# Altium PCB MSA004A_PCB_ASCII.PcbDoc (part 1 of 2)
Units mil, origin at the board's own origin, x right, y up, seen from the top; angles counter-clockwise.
Board outline 2300 x 2720 mil, 2 copper layers (Top Layer, Bottom Layer), stack 62 mil thick; 117 components, 85 nets, 350 pads, 179 vias.
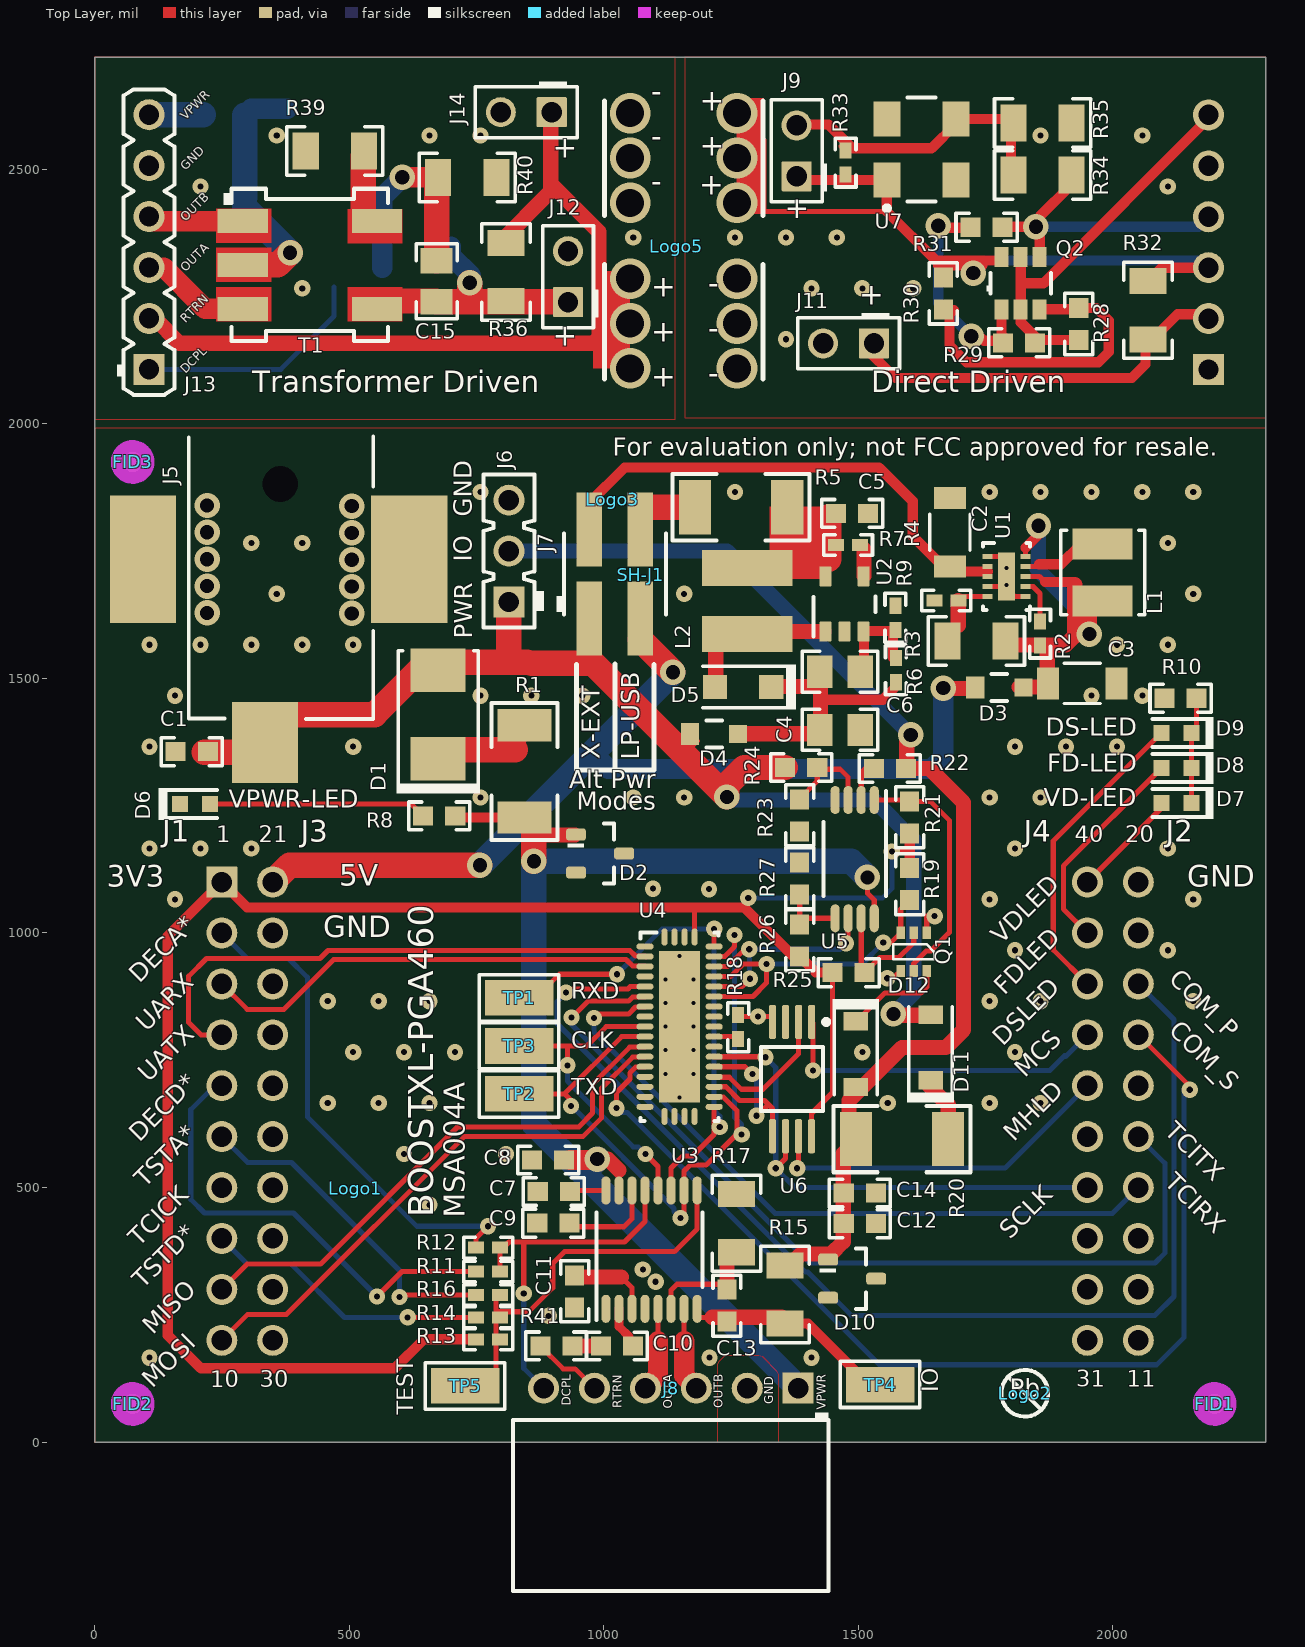
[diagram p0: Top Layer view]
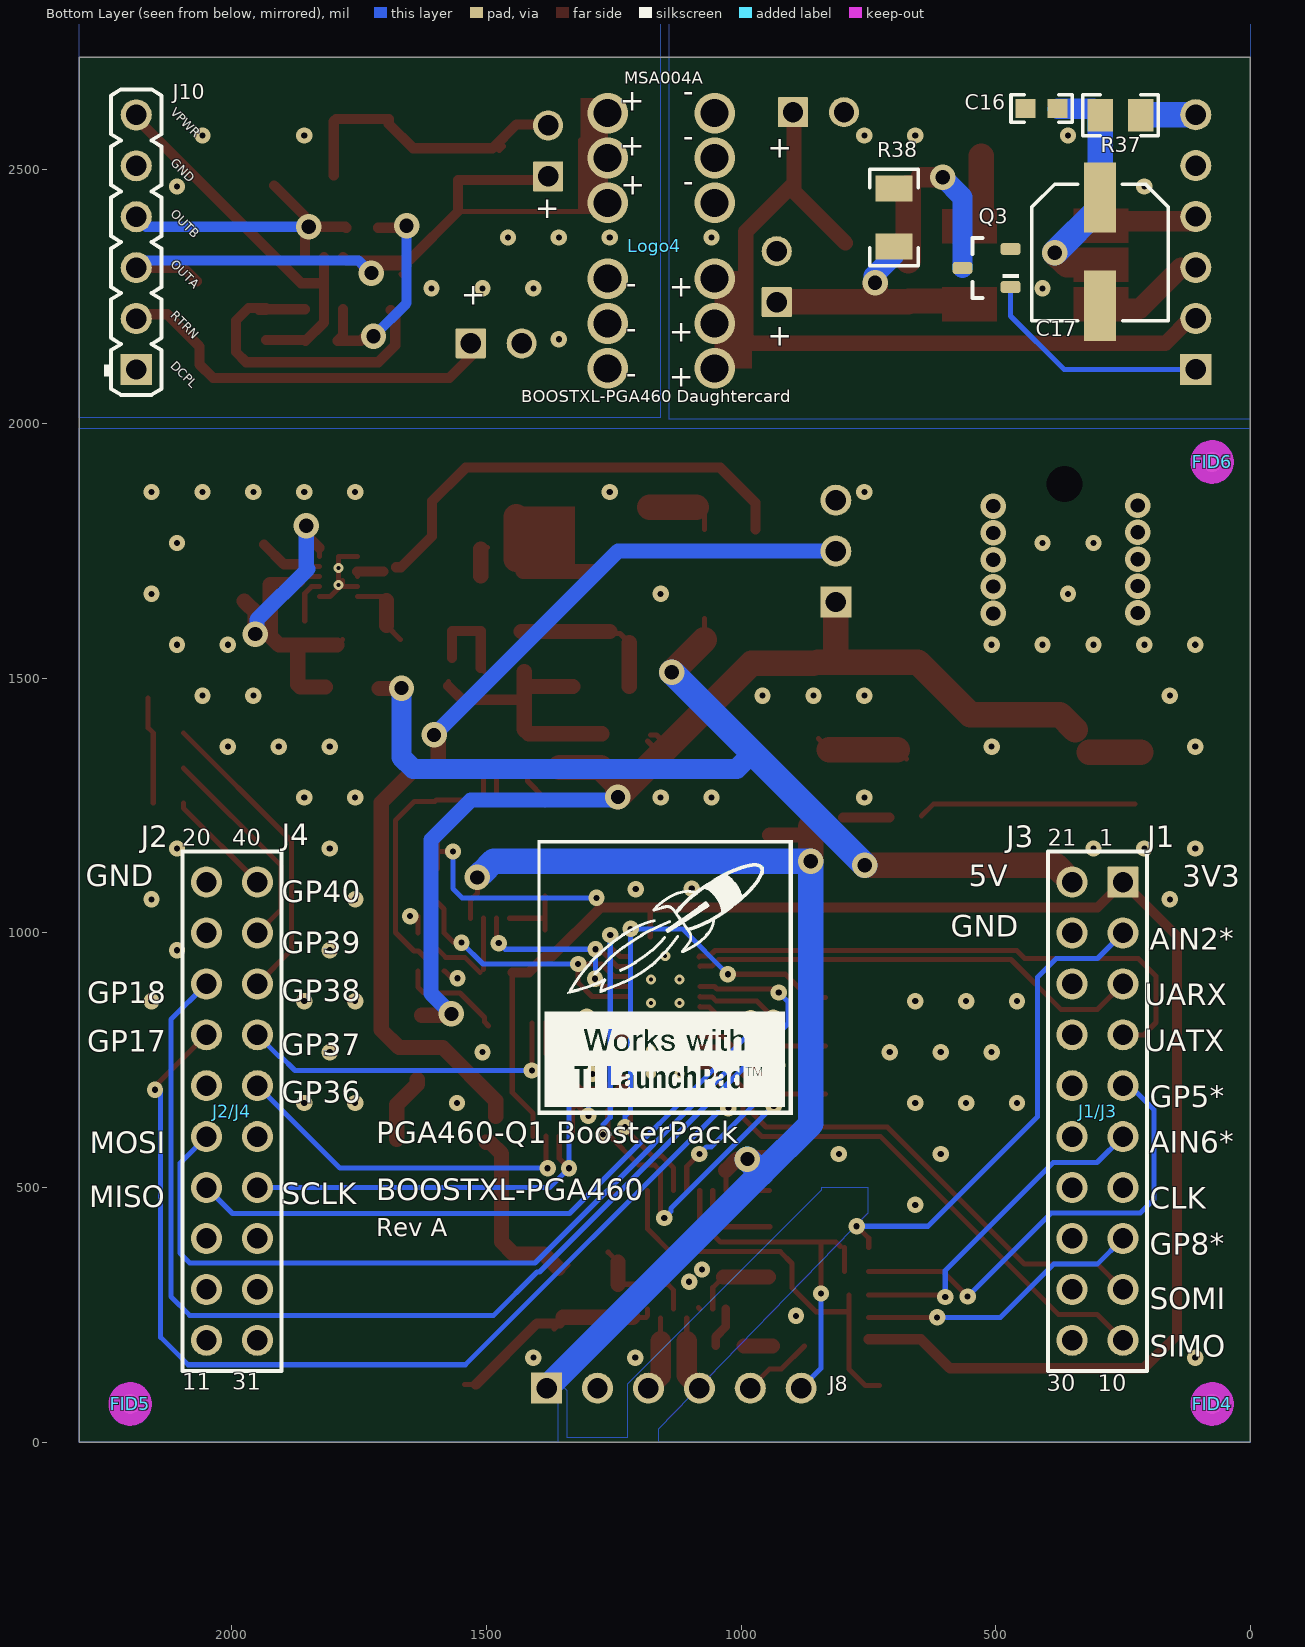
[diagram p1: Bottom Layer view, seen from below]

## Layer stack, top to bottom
Top Solder: solder mask 0.4, Solder Resist, Dk 3.5
Top Layer: signal copper 1.4
Dielectric1: core 59.2, FR-4, Dk 4.8
Bottom Layer: signal copper 1.4
Bottom Solder: solder mask 0.4, Solder Resist, Dk 3.5

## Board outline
0,0 2300,0 2300,2720 0,2720

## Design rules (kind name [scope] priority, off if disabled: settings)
AcuteAngle [All] p0: scope1count=1 scope1_0_kind=Board scope1_0_value=Board scope2count=1 scope2_0_kind=Board scope2_0_value=Board commentlength=0 minimum=4.50000000000000E+0001
AcuteAngle [All] p1: minimum=4.50000000000000E+0001 checktracksonly=FALSE
AssemblyTestPointUsage [All] p0: scope1count=1 scope1_0_kind=Board scope1_0_value=Board scope2count=1 scope2_0_kind=Board scope2_0_value=Board commentlength=0
AssemblyTestPointUsage [All] p1: valid=2
AssemblyTestpoint [All] p0: scope1count=1 scope1_0_kind=Board scope1_0_value=Board scope2count=1 scope2_0_kind=Board scope2_0_value=Board commentlength=0
BoardOutlineClearance [All] p0 off: scope1count=1 scope1_0_kind=Board scope1_0_value=Board scope2count=1 scope2_0_kind=Board scope2_0_value=Board commentlength=172 gap=25 // Protel DXP Scope 1 Expression Was: OnCopper and Not InComponentClass('Logo') and not InComponentClass('FiducialMark') and not InRegion(1000,500,4000,800) and not InPoly
BoardOutlineClearance BoardOutlineClearance_Poly [All] p0 off: scope1count=1 scope1_0_kind=Board scope1_0_value=Board scope2count=1 scope2_0_kind=Board scope2_0_value=Board commentlength=58 gap=25 // Protel DXP Scope 1 Expression Was: OnCopper and IsPoly
BoardOutlineClearance BoardOutlineClearance_MountingHoles [All] p0 off: scope1count=1 scope1_0_kind=Board scope1_0_value=Board scope2count=1 scope2_0_kind=Board scope2_0_value=Board commentlength=86 gap=25 // Protel DXP Scope 1 Expression Was: OnCopper and InComponentClass('Mounting Holes')
BoardOutlineClearance BoardOutlineClearance_MountingHoles [OnCopper and InComponentClass('Mounting Holes')] p1: gap=25
BoardOutlineClearance BoardOutlineClearance_Poly [OnCopper and IsPoly] p2: gap=25
BoardOutlineClearance [OnCopper and Not InComponentClass('Logo') and not InComponentClass('FiducialMark') and not InRegion(1000,500,4000,800) and not InPoly] p3: gap=25
Clearance [All] p0: scope1count=1 scope1_0_kind=Board scope1_0_value=Board scope2count=1 scope2_0_kind=Board scope2_0_value=Board commentlength=0 gap=7.87
Clearance Clearance_Poly [All] p0 off: scope1count=1 scope1_0_kind=Board scope1_0_value=Board scope2count=1 scope2_0_kind=Board scope2_0_value=Board commentlength=48 gap=25 // Protel DXP Scope 1 Expression Was: InPolygon
Clearance Clearance_Keepouts [All] p0 off: scope1count=1 scope1_0_kind=Board scope1_0_value=Board scope2count=1 scope2_0_kind=Board scope2_0_value=Board commentlength=99 gap=0 // Protel DXP Scope 2 Expression Was: ((IsTrack Or IsArc) And Not InPoly) And IsFree and IsKeepOut
Clearance Clearance_1 [All] p0 off: scope1count=1 scope1_0_kind=Board scope1_0_value=Board scope2count=1 scope2_0_kind=Board scope2_0_value=Board commentlength=64 gap=10 // Protel DXP Scope 1 Expression Was: InNamedPolygon('Btm-GND')
Clearance Clearance_2 [All] p0 off: scope1count=1 scope1_0_kind=Board scope1_0_value=Board scope2count=1 scope2_0_kind=Board scope2_0_value=Board commentlength=64 gap=10 // Protel DXP Scope 1 Expression Was: InNamedPolygon('Top-GND')
Clearance Clearance_3 [All] p0 off: scope1count=1 scope1_0_kind=Board scope1_0_value=Board scope2count=1 scope2_0_kind=Board scope2_0_value=Board commentlength=65 gap=10 // Protel DXP Scope 1 Expression Was: InNamedPolygon('Btm-GNDD')
Clearance Clearance_4 [All] p0 off: scope1count=1 scope1_0_kind=Board scope1_0_value=Board scope2count=1 scope2_0_kind=Board scope2_0_value=Board commentlength=65 gap=10 // Protel DXP Scope 1 Expression Was: InNamedPolygon('Top-GNDX')
Clearance Clearance_5 [All] p0 off: scope1count=1 scope1_0_kind=Board scope1_0_value=Board scope2count=1 scope2_0_kind=Board scope2_0_value=Board commentlength=65 gap=10 // Protel DXP Scope 1 Expression Was: InNamedPolygon('Btm-GNDX')
Clearance Clearance_6 [All] p0 off: scope1count=1 scope1_0_kind=Board scope1_0_value=Board scope2count=1 scope2_0_kind=Board scope2_0_value=Board commentlength=65 gap=10 // Protel DXP Scope 1 Expression Was: InNamedPolygon('Top-GNDD')
Clearance Clearance_6 [InNamedPolygon('Top-GNDD')] p1: gap=10
Clearance Clearance_5 [InNamedPolygon('Btm-GNDX')] p2: gap=10
Clearance Clearance_4 [InNamedPolygon('Top-GNDX')] p3: gap=10
Clearance Clearance_3 [InNamedPolygon('Btm-GNDD')] p4: gap=10
Clearance Clearance_2 [InNamedPolygon('Top-GND')] p5: gap=10
Clearance Clearance_1 [InNamedPolygon('Btm-GND')] p6: gap=10
Clearance Clearance_Keepouts [((IsTrack Or IsArc) And Not InPoly) And IsFree and IsKeepOut vs ((IsTrack Or IsArc) And Not InPoly) And IsFree and IsKeepOut] p7: gap=0
Clearance Clearance_Poly [InPolygon] p8: gap=25
Clearance [All] p9: gap=7.87
ComponentClearance ComponentClearance_1 [All] p0: scope1count=1 scope1_0_kind=Board scope1_0_value=Board scope2count=1 scope2_0_kind=Board scope2_0_value=Board commentlength=0 gap=10 collisioncheckmode=3
ComponentClearance ComponentClearance_THtoTH [All] p0 off: scope1count=1 scope1_0_kind=Board scope1_0_value=Board scope2count=1 scope2_0_kind=Board scope2_0_value=Board commentlength=54 gap=30 collisioncheckmode=3 // Protel DXP Scope 2 Expression Was: IsThruComponent
ComponentClearance ComponentClearance_THtoSMT [All] p0 off: scope1count=1 scope1_0_kind=Board scope1_0_value=Board scope2count=1 scope2_0_kind=Board scope2_0_value=Board commentlength=53 gap=40 collisioncheckmode=3 // Protel DXP Scope 2 Expression Was: IsSMTComponent
ComponentClearance ComponentClearance_SmallPassives [All] p0 off: scope1count=1 scope1_0_kind=Board scope1_0_value=Board scope2count=1 scope2_0_kind=Board scope2_0_value=Board commentlength=508 gap=14.96 collisioncheckmode=3 // Protel DXP Scope 2 Expression Was: HasFootprint('0201*') or HasFootprint('0402*') or HasFootprint('0508') or HasFootprint('0603*') or HasFootprint('0612') or HasFootprint('0805*') or HasFootprint('0815*') or HasFootprint('0830*') or HasFootprint('1206*') or HasFootprint('1210*') or HasFootprint('1808*') or HasFootprint('1812*') or HasFootprint('1825*') or HasFootprint('2010*') or HasFootprint('2220*') or HasFootprint('2225*') or HasFootprint('2512*') or HasFootprint('2728*') or HasFootprint('3518*')
ComponentClearance ComponentClearance_MountingHoles [All] p0: scope1count=1 scope1_0_kind=ComponentClass scope1_0_value="Mounting Holes" scope2count=1 scope2_0_kind=Board scope2_0_value=Board commentlength=0 gap=250 collisioncheckmode=3
ComponentClearance ComponentClearance_ScrewToNut [All] p0 off: scope1count=1 scope1_0_kind=Board scope1_0_value=Board scope2count=1 scope2_0_kind=Board scope2_0_value=Board commentlength=71 gap=5 collisioncheckmode=3 // Protel DXP Scope 2 Expression Was: (HasFootprint('Keystone_1902C'))
ComponentClearance ComponentClearance_Logo [All] p0: scope1count=1 scope1_0_kind=ComponentClass scope1_0_value=Logo scope2count=1 scope2_0_kind=Board scope2_0_value=Board commentlength=0 gap=50 collisioncheckmode=3
ComponentClearance ComponentClearance_Shunt [All] p0 off: scope1count=1 scope1_0_kind=ComponentClass scope1_0_value=Header scope2count=1 scope2_0_kind=Board scope2_0_value=Board commentlength=65 gap=0 collisioncheckmode=3 // Protel DXP Scope 2 Expression Was: InComponentClass('Shunt');
ComponentClearance ComponentClearance_MountingHoles_FiducialMarks [All] p0: scope1count=1 scope1_0_kind=ComponentClass scope1_0_value="Mounting Holes" scope2count=1 scope2_0_kind=ComponentClass scope2_0_value=FiducialMark commentlength=0 gap=50 collisioncheckmode=3
ComponentClearance ComponentClearance_1 [All] p1: gap=10 collisioncheckmode=3 verticalgap=10 showdistances=FALSE
ComponentClearance ComponentClearance_MountingHoles_FiducialMarks [InComponentClass('Mounting Holes') vs InComponentClass('FiducialMark')] p2: gap=50 collisioncheckmode=3 verticalgap=10 showdistances=FALSE
ComponentClearance ComponentClearance_Shunt [InComponentClass('Header') vs InComponentClass('Shunt');] p3: gap=0 collisioncheckmode=3 verticalgap=0 showdistances=FALSE
ComponentClearance ComponentClearance_Logo [InComponentClass('Logo')] p4: gap=50 collisioncheckmode=3 verticalgap=10 showdistances=FALSE
ComponentClearance ComponentClearance_ScrewToNut [(HasFootprint('NY PMS 440 0025 PH')) vs (HasFootprint('Keystone_1902C'))] p5: gap=5 collisioncheckmode=3 verticalgap=10 showdistances=FALSE
ComponentClearance ComponentClearance_MountingHoles [InComponentClass('Mounting Holes')] p6: gap=250 collisioncheckmode=3 verticalgap=100000 showdistances=FALSE
ComponentClearance ComponentClearance_SmallPassives [HasFootprint('0201*') or HasFootprint('0402*') or HasFootprint('0508') or HasFootprint('0603*') or HasFootprint('0612') or HasFootprint('0805*') or HasFootprint('0815*') or HasFootprint('0830*') or HasFootprint('1206*') or HasFootprint('1210*') or HasFootprint('1808*') or HasFootprint('1812*') or HasFootprint('1825*') or HasFootprint('2010*') or HasFootprint('2220*') or HasFootprint('2225*') or HasFootprint('2512*') or HasFootprint('2728*') or HasFootprint('3518*') vs HasFootprint('0201*') or HasFootprint('0402*') or HasFootprint('0508') or HasFootprint('0603*') or HasFootprint('0612') or HasFootprint('0805*') or HasFootprint('0815*') or HasFootprint('0830*') or HasFootprint('1206*') or HasFootprint('1210*') or HasFootprint('1808*') or HasFootprint('1812*') or HasFootprint('1825*') or HasFootprint('2010*') or HasFootprint('2220*') or HasFootprint('2225*') or HasFootprint('2512*') or HasFootprint('2728*') or HasFootprint('3518*')] p7: gap=14.96 collisioncheckmode=3 verticalgap=10 showdistances=FALSE
ComponentClearance ComponentClearance_THtoSMT [IsThruComponent vs IsSMTComponent] p8: gap=40 collisioncheckmode=3 verticalgap=30 showdistances=FALSE
ComponentClearance ComponentClearance_THtoTH [IsThruComponent vs IsThruComponent] p9: gap=30 collisioncheckmode=3 verticalgap=30 showdistances=FALSE
DiffPairsRouting [All] p0: scope1count=1 scope1_0_kind=Board scope1_0_value=Board scope2count=1 scope2_0_kind=Board scope2_0_value=Board commentlength=0
DiffPairsRouting [All] p1: maxlimit=100 minlimit=10 mostfreqgap=10 toplayer_minwidth=15 toplayer_maxwidth=15 toplayer_prefwidth=15 bottomlayer_minwidth=15 bottomlayer_maxwidth=15 bottomlayer_prefwidth=15 maxuncoupledlength=1000
FabricationTestPointUsage TestPointUsage [All] p0: scope1count=1 scope1_0_kind=Board scope1_0_value=Board scope2count=1 scope2_0_kind=Board scope2_0_value=Board commentlength=0 valid=2 allowmultiple=FALSE
FabricationTestPointUsage TestPointUsage [All] p1: valid=2 allowmultiple=FALSE
FabricationTestpoint Testpoint [All] p0: scope1count=1 scope1_0_kind=Board scope1_0_value=Board scope2count=1 scope2_0_kind=Board scope2_0_value=Board commentlength=0 side=3 testpointundercomponent=TRUE minsize=40 maxsize=100 preferedsize=60 minholesize=0 maxholesize=40 preferedholesize=32 testpointgrid=1
FabricationTestpoint Testpoint [All] p1: side=3 testpointundercomponent=TRUE minsize=40 maxsize=100 preferedsize=60 minholesize=0 maxholesize=40 preferedholesize=32 testpointgrid=1 allowsidetop=TRUE allowsidebottom=TRUE usegrid=TRUE gridtolerance=0.01
FanoutControl Fanout_Small [All] p0 off: scope1count=1 scope1_0_kind=Board scope1_0_value=Board scope2count=1 scope2_0_kind=Board scope2_0_value=Board commentlength=84 // Protel DXP Scope 1 Expression Was: (CompPinCount < 5)   Fanout_Small (Default Rule)
FanoutControl Fanout_Default [All] p0: scope1count=1 scope1_0_kind=Board scope1_0_value=Board scope2count=1 scope2_0_kind=Board scope2_0_value=Board commentlength=30 // Fanout_Default (Default Rule)
FanoutControl Fanout_SOIC [All] p0 off: scope1count=1 scope1_0_kind=Board scope1_0_value=Board scope2count=1 scope2_0_kind=Board scope2_0_value=Board commentlength=71 // Protel DXP Scope 1 Expression Was: IsSOIC   Fanout_SOIC (Default Rule)
FanoutControl Fanout_BGA [All] p0 off: scope1count=1 scope1_0_kind=Board scope1_0_value=Board scope2count=1 scope2_0_kind=Board scope2_0_value=Board commentlength=69 // Protel DXP Scope 1 Expression Was: IsBGA   Fanout_BGA (Default Rule)
FanoutControl Fanout_LCC [All] p0 off: scope1count=1 scope1_0_kind=Board scope1_0_value=Board scope2count=1 scope2_0_kind=Board scope2_0_value=Board commentlength=69 // Protel DXP Scope 1 Expression Was: IsLCC   Fanout_LCC (Default Rule)
FanoutControl Fanout_LCC [IsLCC] p1: bgadir=Out bgaviamode=Centered fanoutstyle=Auto fanoutdirection=Alternating viagrid=1 // Fanout_LCC (Default Rule)
FanoutControl Fanout_BGA [IsBGA] p2: bgadir=Out bgaviamode=Centered fanoutstyle=Auto fanoutdirection=Alternating viagrid=1 // Fanout_BGA (Default Rule)
FanoutControl Fanout_Default [All] p4: bgadir=Out bgaviamode=Centered fanoutstyle=Auto fanoutdirection=Alternating viagrid=1 // Fanout_Default (Default Rule)
FanoutControl Fanout_Small [(CompPinCount < 5)] p5: bgadir=Out bgaviamode=Centered fanoutstyle=Auto fanoutdirection=OutThenIn viagrid=1 // Fanout_Small (Default Rule)
Height [All] p0: scope1count=1 scope1_0_kind=Board scope1_0_value=Board scope2count=1 scope2_0_kind=Board scope2_0_value=Board commentlength=0
HoleSize [All] p0: scope1count=1 scope1_0_kind=Board scope1_0_value=Board scope2count=1 scope2_0_kind=Board scope2_0_value=Board commentlength=0 absolutevalues=TRUE maxlimit=251 minlimit=7.87 maxpercent=80.000 minpercent=20.000
HoleSize [All] p1: absolutevalues=TRUE maxlimit=251 minlimit=7.87 maxpercent=80.000 minpercent=20.000
HoleToHoleClearance [All] p0: scope1count=1 scope1_0_kind=Board scope1_0_value=Board scope2count=1 scope2_0_kind=Board scope2_0_value=Board commentlength=0
LayerPairs [All] p0: scope1count=1 scope1_0_kind=Board scope1_0_value=Board scope2count=1 scope2_0_kind=Board scope2_0_value=Board commentlength=0 enforce=TRUE
MinimumAnnularRing [All] p0: scope1count=1 scope1_0_kind=Board scope1_0_value=Board scope2count=1 scope2_0_kind=Board scope2_0_value=Board commentlength=0 minimumring=8
MinimumAnnularRing MinimumAnnularRing_ThermalPadVias [All] p0 off: scope1count=1 scope1_0_kind=Board scope1_0_value=Board scope2count=1 scope2_0_kind=Board scope2_0_value=Board commentlength=63 minimumring=5.91 // Protel DXP Scope 1 Expression Was: IsVia and InAnyComponent
MinimumAnnularRing MinimumAnnularRing_ThermalPadVias [IsVia and InAnyComponent] p1: minimumring=5.91
MinimumAnnularRing [All] p2: minimumring=8
MinimumSolderMaskSliver [All] p0: scope1count=1 scope1_0_kind=Board scope1_0_value=Board scope2count=1 scope2_0_kind=Board scope2_0_value=Board commentlength=0
MinimumSolderMaskSliver MinimumSolderMaskSliver_Logo [All] p0: scope1count=1 scope1_0_kind=ComponentClass scope1_0_value=Logo scope2count=1 scope2_0_kind=ComponentClass scope2_0_value=Logo commentlength=0
MinimumSolderMaskSliver MinimumSolderMaskSliver_Logo [InComponentClass('Logo') vs InComponentClass('Logo')] p1: minsoldermaskwidth=0.7
MinimumSolderMaskSliver [All] p2: minsoldermaskwidth=3.94
NetAntennae [All] p0: scope1count=1 scope1_0_kind=Board scope1_0_value=Board scope2count=1 scope2_0_kind=Board scope2_0_value=Board commentlength=0
PasteMaskExpansion [All] p0: scope1count=1 scope1_0_kind=Board scope1_0_value=Board scope2count=1 scope2_0_kind=Board scope2_0_value=Board commentlength=0 expansion=0
PlaneClearance [All] p0: scope1count=1 scope1_0_kind=Board scope1_0_value=Board scope2count=1 scope2_0_kind=Board scope2_0_value=Board commentlength=0 clearance=20
PlaneConnect [All] p0: scope1count=1 scope1_0_kind=Board scope1_0_value=Board scope2count=1 scope2_0_kind=Board scope2_0_value=Board commentlength=0 planeconnectstyle=Relief reliefexpansion=10 reliefentries=4 reliefconductorwidth=10 reliefairgap=10
PlaneConnect [All] p1: planeconnectstyle=Relief reliefexpansion=10 reliefentries=4 reliefconductorwidth=10 reliefairgap=10
PolygonConnect PolygonConnect_2 [All] p0 off: scope1count=1 scope1_0_kind=Board scope1_0_value=Board scope2count=1 scope2_0_kind=Board scope2_0_value=Board commentlength=64 connectstyle=Direct reliefconductorwidth=10 reliefentries=4 polygonreliefangle="90 Angle" // Protel DXP Scope 2 Expression Was: IsNamedPolygon('Btm-GND')
PolygonConnect PolygonConnect_1 [All] p0 off: scope1count=1 scope1_0_kind=Board scope1_0_value=Board scope2count=1 scope2_0_kind=Board scope2_0_value=Board commentlength=64 connectstyle=Direct reliefconductorwidth=10 reliefentries=4 polygonreliefangle="90 Angle" // Protel DXP Scope 2 Expression Was: IsNamedPolygon('Top-GND')
PolygonConnect [All] p0: scope1count=1 scope1_0_kind=Board scope1_0_value=Board scope2count=1 scope2_0_kind=Board scope2_0_value=Board commentlength=0 connectstyle=Relief reliefconductorwidth=10 reliefentries=4 polygonreliefangle="90 Angle"
PolygonConnect PolygonConnect_3 [All] p0 off: scope1count=1 scope1_0_kind=Board scope1_0_value=Board scope2count=1 scope2_0_kind=Board scope2_0_value=Board commentlength=65 connectstyle=Direct reliefconductorwidth=10 reliefentries=4 polygonreliefangle="90 Angle" // Protel DXP Scope 2 Expression Was: IsNamedPolygon('Btm-GNDX')
PolygonConnect PolygonConnect_4 [All] p0 off: scope1count=1 scope1_0_kind=Board scope1_0_value=Board scope2count=1 scope2_0_kind=Board scope2_0_value=Board commentlength=65 connectstyle=Direct reliefconductorwidth=10 reliefentries=4 polygonreliefangle="90 Angle" // Protel DXP Scope 2 Expression Was: IsNamedPolygon('Btm-GNDD')
PolygonConnect PolygonConnect_5 [All] p0 off: scope1count=1 scope1_0_kind=Board scope1_0_value=Board scope2count=1 scope2_0_kind=Board scope2_0_value=Board commentlength=65 connectstyle=Direct reliefconductorwidth=10 reliefentries=4 polygonreliefangle="90 Angle" // Protel DXP Scope 2 Expression Was: IsNamedPolygon('Top-GNDX')
PolygonConnect PolygonConnect_6 [All] p0 off: scope1count=1 scope1_0_kind=Board scope1_0_value=Board scope2count=1 scope2_0_kind=Board scope2_0_value=Board commentlength=65 connectstyle=Direct reliefconductorwidth=10 reliefentries=4 polygonreliefangle="90 Angle" // Protel DXP Scope 2 Expression Was: IsNamedPolygon('Top-GNDD')
PolygonConnect PolygonConnect_6 [All vs IsNamedPolygon('Top-GNDD')] p1: connectstyle=Direct reliefconductorwidth=10 reliefentries=4 polygonreliefangle="90 Angle" airgapwidth=10
PolygonConnect PolygonConnect_5 [All vs IsNamedPolygon('Top-GNDX')] p2: connectstyle=Direct reliefconductorwidth=10 reliefentries=4 polygonreliefangle="90 Angle" airgapwidth=10
PolygonConnect PolygonConnect_4 [All vs IsNamedPolygon('Btm-GNDD')] p3: connectstyle=Direct reliefconductorwidth=10 reliefentries=4 polygonreliefangle="90 Angle" airgapwidth=10
PolygonConnect PolygonConnect_3 [All vs IsNamedPolygon('Btm-GNDX')] p4: connectstyle=Direct reliefconductorwidth=10 reliefentries=4 polygonreliefangle="90 Angle" airgapwidth=10
PolygonConnect PolygonConnect_2 [All vs IsNamedPolygon('Btm-GND')] p5: connectstyle=Direct reliefconductorwidth=10 reliefentries=4 polygonreliefangle="90 Angle" airgapwidth=10
PolygonConnect PolygonConnect_1 [All vs IsNamedPolygon('Top-GND')] p6: connectstyle=Direct reliefconductorwidth=10 reliefentries=4 polygonreliefangle="90 Angle" airgapwidth=10
PolygonConnect [All] p7: connectstyle=Relief reliefconductorwidth=10 reliefentries=4 polygonreliefangle="90 Angle" airgapwidth=10
RoutingCorners [All] p0: scope1count=1 scope1_0_kind=Board scope1_0_value=Board scope2count=1 scope2_0_kind=Board scope2_0_value=Board commentlength=0 cornerstyle=45-Degree minsetback=100 maxsetback=100
RoutingLayers [All] p0: scope1count=1 scope1_0_kind=Board scope1_0_value=Board scope2count=1 scope2_0_kind=Board scope2_0_value=Board commentlength=0 top layer=Automatic bottom layer=Automatic
RoutingPriority [All] p0: scope1count=1 scope1_0_kind=Board scope1_0_value=Board scope2count=1 scope2_0_kind=Board scope2_0_value=Board commentlength=0
RoutingTopology [All] p0: scope1count=1 scope1_0_kind=Board scope1_0_value=Board scope2count=1 scope2_0_kind=Board scope2_0_value=Board commentlength=0 topology=Shortest
RoutingVias [All] p0: scope1count=1 scope1_0_kind=Board scope1_0_value=Board scope2count=1 scope2_0_kind=Board scope2_0_value=Board commentlength=0 holewidth=16 width=34 viastyle="Through Hole" minholewidth=7.87 minwidth=26 maxholewidth=40 maxwidth=65
RoutingVias ThermalPadVias [All] p0 off: scope1count=1 scope1_0_kind=Board scope1_0_value=Board scope2count=1 scope2_0_kind=Board scope2_0_value=Board commentlength=63 holewidth=7.87 width=19.68 viastyle="Through Hole" minholewidth=7.87 minwidth=19.68 maxholewidth=12.99 maxwidth=23.62 // Protel DXP Scope 1 Expression Was: IsVia and InAnyComponent
RoutingVias ThermalPadVias [IsVia and InAnyComponent] p1: holewidth=7.87 width=19.68 viastyle="Through Hole" minholewidth=7.87 minwidth=19.68 maxholewidth=12.99 maxwidth=23.62
RoutingVias [All] p2: holewidth=16 width=34 viastyle="Through Hole" minholewidth=7.87 minwidth=26 maxholewidth=40 maxwidth=65
ShortCircuit [All] p0: scope1count=1 scope1_0_kind=Board scope1_0_value=Board scope2count=1 scope2_0_kind=Board scope2_0_value=Board commentlength=0 allowed=FALSE
SilkToBoardRegionClearance [All] p0 off: scope1count=1 scope1_0_kind=Board scope1_0_value=Board scope2count=1 scope2_0_kind=Board scope2_0_value=Board commentlength=130 // Protel DXP Scope 1 Expression Was: Not ((IsComment or IsDesignator) And (Hide <> 'False')) and not InRegion(1000,500,4000,800)
SilkToBoardRegionClearance [Not ((IsComment or IsDesignator) And (Hide <> 'False')) and not InRegion(1000,500,4000,800)] p1:
SilkToSilkClearance [All] p0: scope1count=1 scope1_0_kind=Board scope1_0_value=Board scope2count=1 scope2_0_kind=Board scope2_0_value=Board commentlength=0
SilkToSilkClearance SilkToSilkClearance_Pb-FreeLogo [All] p0 off: scope1count=1 scope1_0_kind=Board scope1_0_value=Board scope2count=1 scope2_0_kind=Board scope2_0_value=Board commentlength=120 // Protel DXP Scope 2 Expression Was: (HasFootprint('Pb-Free_Overlay_Medium') OR HasFootprint('Pb-Free_Overlay_Small'))
SilkToSilkClearance SilkToSilkClearance_Pb-FreeLogo [(HasFootprint('Pb-Free_Overlay_Medium') OR HasFootprint('Pb-Free_Overlay_Small')) vs (HasFootprint('Pb-Free_Overlay_Medium') OR HasFootprint('Pb-Free_Overlay_Small'))] p1: silktosilkclearance=0
SilkToSilkClearance [All] p2: silktosilkclearance=4
SilkToSolderMaskClearance "Silk to Solder Mask Opening" [All] p0: scope1count=1 scope1_0_kind=Board scope1_0_value=Board scope2count=1 scope2_0_kind=Board scope2_0_value=Board commentlength=0
SilkToSolderMaskClearance SilkToComponentPadClearance [All] p0 off: scope1count=1 scope1_0_kind=Board scope1_0_value=Board scope2count=1 scope2_0_kind=Board scope2_0_value=Board commentlength=63 // Protel DXP Scope 1 Expression Was: IsPad and InAnycomponent
SilkToSolderMaskClearance SilkToComponentPadClearance [IsPad and InAnycomponent] p1: minsilkscreentomaskgap=5 clearancetoexposedcopper=TRUE
SilkToSolderMaskClearance "Silk to Solder Mask Opening" [All] p2: minsilkscreentomaskgap=4 clearancetoexposedcopper=FALSE
SolderMaskExpansion [All] p0: scope1count=1 scope1_0_kind=Board scope1_0_value=Board scope2count=1 scope2_0_kind=Board scope2_0_value=Board commentlength=0 expansion=1.97
SolderMaskExpansion [All] p1: expansion=1.97
UnRoutedNet [All] p0: scope1count=1 scope1_0_kind=Board scope1_0_value=Board scope2count=1 scope2_0_kind=Board scope2_0_value=Board commentlength=0
UnpouredPolygon [All] p0: scope1count=1 scope1_0_kind=Board scope1_0_value=Board scope2count=1 scope2_0_kind=Board scope2_0_value=Board commentlength=0
Width [All] p0: scope1count=1 scope1_0_kind=Board scope1_0_value=Board scope2count=1 scope2_0_kind=Board scope2_0_value=Board commentlength=0 maxlimit=100 minlimit=6 preferedwidth=10
Width [All] p1: maxlimit=100 minlimit=6 preferedwidth=10 checkconnectedcopper=TRUE
15 further rules are at their usual default settings.

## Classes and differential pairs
component class MSA004A_PWR: C1 C2 C3 C4 C5 C6 D1 D2 D3 D4 D5 D6 D7 D8 D9 J5 J6 J7 L1 L2 R1 R2 R3 R4 R5 R6 R7 R8 R9 R10 U1 U2
component class MSA004A_XDCR: C15 C16 C17 H1 J9 J10 J11 J12 J13 J14 Q2 Q3 R28 R29 R30 R31 R32 R33 R34 R35 R36 R37 R38 R39 R40 T1 U7
component class MSA004A_USSC: C7 C8 C9 C10 C11 C12 C13 C14 D10 D11 D12 J1/J3 J2/J4 J8 Q1 R11 R12 R13 R14 R15 R16 R17 R18 R19 R20 R21 R22 R23 R24 R25 R26 R27 R41 TP1 TP2 TP3 TP4 TP5 U3 U4 U5 U6
component class Header: J6 J7 J9 J10 J11 J12 J13 J14
component class AssemblyNote: ZZ1 ZZ2 ZZ3 ZZ4 ZZ5
component class FiducialMark: FID1 FID2 FID3 FID4 FID5 FID6
component class MSA004A_HW: FID1 FID2 FID3 FID4 FID5 FID6 Logo1 Logo2 Logo3 Logo4 Logo5 SH-J1 ZZ1 ZZ2 ZZ3 ZZ4 ZZ5
component class Logo: Logo1 Logo4 Logo5

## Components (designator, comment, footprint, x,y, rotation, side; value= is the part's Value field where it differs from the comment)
C1 "C1608X5R1H474K080AB" 0603 191,1356 r180 top
C2 "GRM31CR71H225KA88L" 1206_180 1680,1787 r90 top
C3 "GRM31CR61A226KE19L" 1206_180 1940,1490 r0 top
C4 "GRM21BR61C106KE15L" 0805_HV 1464,1399 r0 top
C5 "GRM188R61A475MAAJ" 0603 1488,1824 r0 top
C6 "CC0805KRX7R9BB102" 0805_HV 1464,1513 r0 top
C7 "C1608X7R1H104K080AA" 0603 902,492 r180 top
C8 "C1608X7R1H104K080AA" 0603 891,554 r180 top
C9 "C1608X7R1H104K080AA" 0603 901,430 r180 top
C10 "GRM1885C2A391JA01D" 0603 1026,189 r180 top
C11 "GRM188R71H333KA61D" 0603 943,296 r270 top
C12 "C1608X7R1H104K080AA" 0603 1503,429 r0 top
C13 "C1608X7R1H104K080AA" 0603 1242,268 r90 top
C14 "C0603C221K5RACTU" 0603 1503,489 r0 top
C15 "GRM2165C2A152JA01D" 0805_HV 672,2280 r90 top
C16 "C1608X7R1H104K080AA" 0603 410,2619 r180 bottom
C17 "EMVA350ADA101MF80G" CAPSMT_62_F80 295,2338 r270 bottom
D1 "B260-13-F" SMB 675,1429 r90 top
D2 "SZMMBZ27VCLT1G" SOT-23 993,1156 r0 top
D3 "DB2130200L" SMini2-F5-B 1777,1482 r0 top
D4 "DB2130200L" SMini2-F5-B 1217,1391 r0 top
D5 "PMEG6010CEH,115" SOD-123F 1274,1483 r180 top
D6 "LTST-C191KFKT" LTST-C191_Orange 197,1253 r180 top
D7 "LTST-C191KRKT" LTST-C191_Red 2125,1255 r0 top
D8 "LTST-C191KRKT" LTST-C191_Red 2125,1324 r0 top
D9 "LTST-C191KRKT" LTST-C191_Red 2125.03,1392.97 r0 top
D10 "SZMMBZ27VCLT1G" SOT-23 1488,321 r0 top
D11 "BAV3004W-7-F" SOD-123 1642,775 r90 top
D12 "BAV3004W-7-F" SOD-123 1495,762 r270 top
FID1 "Fiducial" Fiducial10-20 2200,75 r0 top
FID2 "Fiducial" Fiducial10-20 75,75 r0 top
FID3 "Fiducial" Fiducial10-20 75,1925 r0 top
FID4 "Fiducial" Fiducial10-20 75,75 r180 bottom
FID5 "Fiducial" Fiducial10-20 2200,75 r180 bottom
FID6 "Fiducial" Fiducial10-20 75,1925 r180 bottom
J1/J3 "SSQ-110-03-T-D" BoosterPack_40pin_J1J3 300,650 r180 bottom locked
J2/J4 "SSQ-110-03-T-D" BoosterPack_40pin_J2J4 2000,650 r180 bottom locked
J5 "RASM712PX" Switchcraft_RASM712PX 365,2000 r180 top
J6 "TSW-103-07-T-S" Samtec_TSW-103-07-T-S 814,1750 r90 top
J7 "0015912040" Molex_0015912040 1022,1705 r90 top
J8 "PPPC061LGBN-RC" Sullins_xPxC061LGBN 1132,106 r270 top
J9 "PEC02SAAN" CONN_PEC02SAAN 1379,2536 r90 top
J10 "PBC06SAAN" Sullins_PxC06SAAN 2187.95,2356.62 r90 bottom
J11 "PEC02SAAN" CONN_PEC02SAAN 1481,2158 r180 top
J12 "PEC02SAAN" CONN_PEC02SAAN 930,2289 r90 top
J13 "PBC06SAAN" Sullins_PxC06SAAN 107.05,2357 r90 top
J14 "PEC02SAAN" CONN_PEC02SAAN 848,2612 r180 top
L1 "LQH44PN100MP0L" IND_LQH44P 1980,1708 r270 top
L2 "SDR0403-100ML" SDR0403 1282,1652 r270 top
Logo1 "Texas Instruments" TI_Stacked_Overlay_Small 512,499 r90 top
Logo2 "Pb-Free Symbol" Pb-Free_Overlay_Small 1827,96 r0 top
Logo3 "FCC disclaimer" FCC_disclaimer 1017,1852 r0 top
Logo4 "Texas Instruments" TI_Symbol_Overlay_Small 1170.12,2349.78 r180 bottom
Logo5 "Texas Instruments" TI_Symbol_Overlay_Small 1142.74,2348.5 r0 top
Q1 "2N7002DW" SOT-363 1609,963 r270 top
Q2 "FDC6506P" superSOT-6 1819,2276 r90 top
Q3 "BSS123" SOT-23 518,2306 r0 bottom
R1 "CRCW201010R0JNEF" 2010 844.56,1317.46 r270 top
R2 "CRCW0402100KFKED" 0402 1857,1588 r90 top
R3 "RC1206FR-072M2L" 1206 1732,1573 r0 top
R4 "CRCW0402383KFKED" 0402 1673,1653 r180 top
R5 "CRCW201033R0JNEF" 2010 1270,1836 r0 top
R6 "CRCW040251K1FKED" 0402 1574,1516 r270 top
R7 "CRCW040210K0FKED" 0402 1480,1762 r0 top
R8 "RC0603JR-0751KL" 0603 677,1230 r180 top
R9 "CRCW040210K0FKED" 0402 1573,1619 r90 top
R10 "RC0603JR-0710KL" 0603 2133,1461 r180 top
R11 "CRCW04020000Z0ED" 0402 773,335 r180 top
R12 "CRCW04020000Z0ED" 0402 773,382 r180 top
R13 "CRCW0402100KJNED" 0402 773,201.79 r180 top
R14 "CRCW04020000Z0ED" 0402 773,245 r180 top
R15 "CRCW12060000Z0EA" 1206 1356,290 r270 top
R16 "CRCW04020000Z0ED" 0402 773,289 r180 top
R17 "CRCW12060000Z0EA" 1206 1261,430 r270 top
R18 "CRCW040210K0FKED" 0402 1264,815 r90 top
R19 "CRCW06031K00JNEA" 0603 1601,1096 r270 top
R20 "CRCW20101K00JNEF" 2010 1586,595 r0 top
R21 "CRCW06031K00JNEA" 0603 1601,1227 r270 top
R22 "CRCW0603100KJNEA" 0603 1562,1323 r0 top
R23 "CRCW0603100KJNEA" 0603 1385,1231 r90 top
R24 "CRCW0603100KJNEA" 0603 1388,1325 r180 top
R25 "CRCW06031K00JNEA" 0603 1481,922 r180 top
R26 "CRCW0603100KJNEA" 0603 1385,985.5 r90 top
R27 "CRCW0603100KJNEA" 0603 1385,1107 r270 top
R28 "CRCW06031K00JNEA" 0603 1933,2196 r270 top
R29 "CRCW06031K00JNEA" 0603 1816,2159 r0 top
R30 "CRCW06031K00JNEA" 0603 1667,2256 r90 top
R31 "CRCW06031K00JNEA" 0603 1752,2386 r0 top
R32 "CRCW12060000Z0EA" 1206 2069,2223 r270 top
R33 "CRCW04022K00JNED" 0402 1475,2513 r270 top
R34 "CRCW12060000Z0EA" 1206 1862,2489 r180 top
R35 "CRCW12060000Z0EA" 1206 1862,2591 r180 top
R36 "CRCW12060000Z0EA" 1206 808,2298 r90 top
R37 "CRCW0805100RJNEA" 0805_HV 255,2606 r0 bottom
R38 "CRCW12062K70JNEA" 1206 700,2405 r270 bottom
R39 "CRCW12060000Z0EA" 1206 472,2536 r0 top
R40 "CRCW12060000Z0EA" 1206 732,2484 r180 top
R41 "CRCW0603100RFKEA" 0603 907,189 r0 top
SH-J1 "60900213421" Wurth_60900213421 1073,1704 r90 top
T1 "B78416A2232A003" TDK_B78416A2232A003 423,2312 r0 top
TP1 "RXD" Testpoint_Keystone_Miniature 834,873 r0 top
TP2 "TXD" Testpoint_Keystone_Miniature 834,684 r0 top
TP3 "CLK" Testpoint_Keystone_Miniature 834,778 r180 top
TP4 "IO" Testpoint_Keystone_Miniature 1543,113 r180 top
TP5 "TEST" Testpoint_Keystone_Miniature 728,111 r0 top
U1 "TPS62175DQCR" DQC0010A 1791,1700 r0 top
U2 "LMR62421XMFX/NOPB" DBV0005A_N 1473,1646 r90 top
U3 "PGA460TPWRQ1" PW0016A_N 1094,378 r90 top
U4 "TS3L501ERUAR" RUA0042A 1149,816 r0 top
U5 "LM2903PW" PW0008A_N 1493,1145 r270 top
U6 "23LC512-I/ST" TSSOP-8 1370,713 r270 top
U7 "MA40H1S-R" MA40H1S 1624,2538.62 r90 top
ZZ1 "These assemblies are ESD sensitive, ESD precautions shall be observed." AssemblyNote 185,3829.11 r0 top
ZZ2 "These assemblies must be clean and free from flux and all contaminants. Use of no clean flux is not acceptable." AssemblyNote 185,3740.56 r0 top
ZZ3 "These assemblies must comply with workmanship standards IPC-A-610 Class 2, unless otherwise specified." AssemblyNote 185,3652 r0 top
ZZ4 "Add score line between boards for separation post-assembly." AssemblyNote 185,3528 r0 top
ZZ5 "Connect MA58MF14-7N (H1) XDCR to J12 holes. Black wired pin must be connected to GND_XD (-)." AssemblyNote 185,3448 r0 top

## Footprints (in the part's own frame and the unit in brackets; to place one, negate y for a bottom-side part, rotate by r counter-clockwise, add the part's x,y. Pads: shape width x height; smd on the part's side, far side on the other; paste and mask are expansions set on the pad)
0402 [mm] "0402 from SM-752 data"
  rect 0.8x0.6 smd: 1(-0.6,0) 2(0.6,0)
  silkscreen extent -1.22,-0.52 1.22,0.52
0603 [mm] "0603 from SM-752 data"
  rect 1x0.95 smd: 1(-0.8,0) 2(0.8,0)
  silkscreen extent -1.52,-0.69 1.52,0.69
0805_HV [mil] "0805 with 30mil clearance between pads"
  rect 50x63 smd: 1(-40,0) 2(40,0)
  silkscreen extent -74,-40 74,40
1206 [mm] "1206 from SM-752 data"
  rect 1.3x1.85 smd: 1(-1.45,0) 2(1.45,0)
  silkscreen extent -2.4,-1.21 2.4,1.21
1206_180 [mm] "1206_180"
  rect 1.1x1.6 smd: 1(-1.7,0) 2(1.7,0)
  silkscreen extent -0.9,-1 0.9,1
2010 [mm] "Chip Capacitor, Body 5.08x2.54mm, IPC Medium Density"
  rect 1.6x2.7 smd: 1(-2.3,0) 2(2.3,0)
  silkscreen extent -3.42,-1.65 3.42,1.65
AssemblyNote [mil] "Assembly Note"
BoosterPack_40pin_J1J3 [mm] "Receptacle, 2.54mm, 10x2, TH"
  rrect6% 1.55x1.55 hole 1.02: 1(1.27,11.43)
  round 1.55 hole 1.02: 2(1.27,8.89) 3(1.27,6.35) 4(1.27,3.81) 5(1.27,1.27) 6(1.27,-1.27) 7(1.27,-3.81) 8(1.27,-6.35) 9(1.27,-8.89) 10(1.27,-11.43) 21(-1.27,11.43) 22(-1.27,8.89) 23(-1.27,6.35) 24(-1.27,3.81) 25(-1.27,1.27) 26(-1.27,-1.27) 27(-1.27,-3.81) 28(-1.27,-6.35) 29(-1.27,-8.89) 30(-1.27,-11.43)
  silkscreen extent -2.48,-12.95 2.48,12.95
BoosterPack_40pin_J2J4 [mm] "Receptacle, 2.54mm, 10x2, TH"
  round 1.55 hole 1.02: 11(-1.27,-11.43) 12(-1.27,-8.89) 13(-1.27,-6.35) 14(-1.27,-3.81) 15(-1.27,-1.27) 16(-1.27,1.27) 17(-1.27,3.81) 18(-1.27,6.35) 19(-1.27,8.89) 20(-1.27,11.43) 31(1.27,-11.43) 32(1.27,-8.89) 33(1.27,-6.35) 34(1.27,-3.81) 35(1.27,-1.27) 36(1.27,1.27) 37(1.27,3.81) 38(1.27,6.35) 39(1.27,8.89) 40(1.27,11.43)
  silkscreen extent -2.48,-12.95 2.48,12.95
CAPSMT_62_F80 [mm] "6.3 x 7.7mm:  Chemi-Con F80"
  rect 3.5x1.6 smd: 1(-2.7,0) 2(2.7,0)
  silkscreen extent -3.36,-3.4 3.44,3.4
CONN_PEC02SAAN [mm] "SULLINS"
  rrect7% 1.5x1.5 hole 1.016: 1(-1.27,0)
  round 1.5 hole 1.016: 2(1.27,0)
  silkscreen extent -2.54,-1.52 2.54,1.27
DBV0005A_N [mm] "SOT23, 5-Leads, Body 2.9x1.6mm, Pitch 0.95mm, Lead Span 2.8mm, IPC Medium Density"
  rrect17% 1x0.6 smd: 1(-1.375,0.95) 2(-1.375,0) 3(-1.375,-0.95) 4(1.375,-0.95) 5(1.375,0.95)
  silkscreen extent -1.62,-1.55 0.38,1.55
DQC0010A [mm] "SON, 10-Leads, Body 2x3mm, Pitch 0.5mm, Thermal Pad 2.4x0.84mm"
  rect 0.5x0.25 smd: 1(-0.95,1) 2(-0.95,0.5) 3(-0.95,0) 4(-0.95,-0.5) 5(-0.95,-1) 6(0.95,-1) 7(0.95,-0.5) 8(0.95,0) 9(0.95,0.5) 10(0.95,1)
  rect 0.84x2.4 smd paste-0.42: 11(0,0)
  silkscreen extent -1.18,-1.67 1.18,1.67
FCC_disclaimer [mil]
Fiducial10-20 [mm]
  round 1 smd mask+0: 1(0,0)
  Top Layer keep-out circle w1.178: c0,0 r0.5
IND_LQH44P [mm] "Murata"
  rect 1.55x3 smd: 1(-1.425,0) 2(1.425,0)
  silkscreen extent -2.1,-2.1 2.1,2.1
LTST-C191_Orange [mm] "SMD, 2-Leads, Body 1.6x0.8mm"
  rect 0.8x0.8 smd: 1(-0.75,0) 2(0.75,0)
  silkscreen extent -1.1,-0.8 1.8,0.8
LTST-C191_Red [mm] "SMD, 2-Leads, Body1.6x0.8mm"
  rect 0.8x0.8 smd: 1(-0.75,0) 2(0.75,0)
  silkscreen extent -1.2,-0.8 1.85,0.8
MA40H1S [mm] "SMD, 4-Leads, Body 5.3x5.3mm"
  rect 1.75x1.35 smd: 1(-1.525,1.725) 2(-1.525,-1.725) 3(1.525,-1.725) 4(1.525,1.725)
  silkscreen extent -3.05,-0.7 2.6,1.85
Molex_0015912040 [mm] "Header, 2.54mm, 2x2, Gold, SMT"
  rect 3.68x1.27 smd: 1(-2.22,1.27) 2(2.22,1.27) 3(-2.22,-1.27) 4(2.22,-1.27)
  silkscreen extent -2.03,-2.54 2.03,2.9
Pb-Free_Overlay_Small [mil]
  silkscreen extent -46,-46 46,46
PW0008A_N [mm] "TSOP, 8-Leads, Body 3x4.4mm, Pitch 0.65mm, IPC Medium Density"
  oval 1.4x0.45 smd: 1(-2.95,0.975) 2(-2.95,0.325) 3(-2.95,-0.325) 4(-2.95,-0.975) 5(2.95,-0.975) 6(2.95,-0.325) 7(2.95,0.325) 8(2.95,0.975)
  silkscreen extent -3.4,-1.55 1.85,1.55
PW0016A_N [mm] "TSOP, 16-Leads, Body 5x4.4mm, Pitch 0.65mm, IPC Medium Density"
  oval 1.4x0.45 smd: 1(-2.95,2.275) 2(-2.95,1.625) 3(-2.95,0.975) 4(-2.95,0.325) 5(-2.95,-0.325) 6(-2.95,-0.975) 7(-2.95,-1.625) 8(-2.95,-2.275) 9(2.95,-2.275) 10(2.95,-1.625) 11(2.95,-0.975) 12(2.95,-0.325) 13(2.95,0.325) 14(2.95,0.975) 15(2.95,1.625) 16(2.95,2.275)
  silkscreen extent -3.5,-2.55 1.85,2.75
RUA0042A [mm] "QFN, 42-Leads, Body 3.5x9mm, Pitch 0.5mm, Thermal Pad 2.05x7.55mm, TI Recommended"
  oval 0.85x0.3 smd: 1(-1.725,4) 2(-1.725,3.5) 3(-1.725,3) 4(-1.725,2.5) 5(-1.725,2) 6(-1.725,1.5) 7(-1.725,1) 8(-1.725,0.5) 9(-1.725,0) 10(-1.725,-0.5) 11(-1.725,-1) 12(-1.725,-1.5) 13(-1.725,-2) 14(-1.725,-2.5) 15(-1.725,-3) 16(-1.725,-3.5) 17(-1.725,-4) 22(1.725,-4) 23(1.725,-3.5) 24(1.725,-3) 25(1.725,-2.5) 26(1.725,-2) 27(1.725,-1.5) 28(1.725,-1) 29(1.725,-0.5) 30(1.725,0) 31(1.725,0.5) 32(1.725,1) 33(1.725,1.5) 34(1.725,2) 35(1.725,2.5) 36(1.725,3) 37(1.725,3.5) 38(1.725,4)
  oval 0.3x0.85 smd: 18(-0.75,-4.475) 19(-0.25,-4.475) 20(0.25,-4.475) 21(0.75,-4.475) 39(0.75,4.475) 40(0.25,4.475) 41(-0.25,4.475) 42(-0.75,4.475)
  rect 2.05x7.55 smd paste-1.25: 43(0,0)
  silkscreen extent -1.95,-4.7 1.95,4.7
Samtec_TSW-103-07-T-S [mm] "Header, 2.54 mm, 3x1, TH"
  rect 1.55x1.55 hole 1.02: 1(-2.54,0)
  round 1.55 hole 1.02: 2(0,0) 3(2.54,0)
  silkscreen extent -3.81,-1.75 3.81,1.27
SDR0403 [mm] "BOURNS"
  rect 1.8x4.5 smd: 1(-1.65,0) 2(1.65,0)
SMB [mil] "Molded Diode, 2-Leads, Body 5.4x3.6mm, IPC Medium Density, based on OnSemi component dimensions"
  rect 85x107.99 smd: 1(-87.01,0) 2(87.01,0)
  silkscreen extent -155,-82 125,82
SMini2-F5-B [mm] "Panasonic"
  rect 0.9x1.1 smd: 1(-1.2,0)
  rect 0.9x0.9 smd: 2(1.2,0)
  silkscreen extent -0.38,-0.67 0.38,0.67
SOD-123 [mm] "On Semi recommended land pattern"
  rect 0.915x1.22 smd: 1(-1.637,0) 2(1.637,0)
  silkscreen extent -2.74,-1.17 2.03,1.17
SOD-123F [mm] "NXP recommended land pattern"
  rect 1.2x1.2 smd paste-0.05: 1(-1.4,0) 2(1.4,0)
  silkscreen extent -2.64,-1.12 2.01,1.12
SOT-23 [mm] "SOT23, 3-Leads, Body 2.9x1.3mm, Pitch 0.95mm, Lead Span 2.5mm, IPC Medium Density"
  rrect50% 1x0.6 smd: 1(-1.2,0.95) 2(-1.2,-0.95) 3(1.2,0)
  silkscreen extent -1.62,-1.5 0.7,1.5
SOT-363 [mm]
  rect 0.6x0.42 smd mask+0: 1(-0.95,0.65) 2(-0.95,0) 3(-0.95,-0.65) 4(0.95,-0.65) 5(0.95,0) 6(0.95,0.65)
  silkscreen extent -0.38,-1.02 0.38,1.02
Sullins_PxC06SAAN [mil] "Header, 2.54mm, 6x1, TH"
  rect 61.02x61.02 hole 40: 1(-250,0)
  round 61.02 hole 40: 2(-150,0) 3(-50,0) 4(50,0) 5(150,0) 6(250,0)
  silkscreen extent -300,-50 300,63
Sullins_xPxC061LGBN [mm] "Receptacle, 2.54mm, 6x1, R/A, TH"
  rect 1.55x1.55 hole 1.02: 1(0,6.35)
  round 1.55 hole 1.02: 2(0,3.81) 3(0,1.27) 4(0,-1.27) 5(0,-3.81) 6(0,-6.35)
  silkscreen extent 1.21,-7.87 10.11,7.87
superSOT-6 [mm] "SOP, 6-Leads, Body 1.6x2.9mm, Pitch 0.95mm"
  rect 1x0.7 smd: 1(-1.3,0.95) 2(-1.3,0) 3(-1.3,-0.95) 4(1.3,-0.95) 5(1.3,0) 6(1.3,0.95)
  silkscreen extent -0.5,-1.5 0.5,1.7
Switchcraft_RASM712PX [mm] "SWITCHCRAFT"
  round 1.524 hole 1.78 unplated: 0(0,3)
  rect 3.3x4.06 smd: 1(0.76,15.9)
  rect 3.3x6.35 smd: 2(6.86,6.76)
  rect 3.81x6.35 smd: 3(-6.43,6.76)
  silkscreen extent -4.62,0.62 4.57,14.72
TDK_B78416A2232A003 [mm] "SMT, 5-Leads, Body 8.8x7.6mm"
  rect 2.5x1.2 smd: 1(-3.35,2.2) 2(-3.35,0) 3(-3.35,-2.2) 4(3.35,-2.2) 6(3.35,2.2)
  silkscreen extent -4.3,-3.8 3.9,3.8
Testpoint_Keystone_Miniature [mil] "Miniature SMT test point"
  rect 135x70 smd: 1(0,0)
  silkscreen extent -78,-46 78,45
TI_Stacked_Overlay_Small [mil]
TI_Symbol_Overlay_Small [mil]
TSSOP-8 [mm] "TSSOP, 8-Leads, Body 3.1x4.5mm (max), Pitch 0.65mm, IPC Medium Density"
  rrect50% 1.7x0.35 smd: 1(-2.85,0.975) 2(-2.85,0.325) 3(-2.85,-0.325) 4(-2.85,-0.975) 5(2.85,-0.975) 6(2.85,-0.325) 7(2.85,0.325) 8(2.85,0.975)
  silkscreen extent -2.97,-1.55 1.6,1.83
Wurth_60900213421 [mil] "Shunt, 2.54mm, Black"
  round 1 on Mech3: 0(0,0)

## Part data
C1: "CAP, CERM, 0.47 µF, 50 V, +/- 10%, X5R, 0603"
C2: "CAP, CERM, 2.2 µF, 50 V, +/- 10%, X7R, 1206"
C3: "CAP, CERM, 22 µF, 10 V, +/- 10%, X5R, 1206"
C4: "CAP, CERM, 10 µF, 16 V, +/- 10%, X5R, 0805"
C5: "CAP, CERM, 4.7 µF, 10 V, +/- 20%, X5R, 0603"
C6: "CAP, CERM, 1000 pF, 50 V, +/- 10%, X7R, 0805"
C7 C8 C9 C12 C13 C16: "CAP, CERM, 0.1 µF, 50 V, +/- 10%, X7R, 0603"
C10: "CAP, CERM, 390 pF, 100 V, +/- 5%, C0G/NP0, 0603"
C11: "CAP, CERM, 0.033 µF, 50 V, +/- 10%, X7R, 0603"
C14: "CAP, CERM, 220 pF, 50 V, +/- 10%, X7R, 0603"
C15: "CAP, CERM, 1500 pF, 100 V, +/- 5%, C0G/NP0, 0805"
C17: "CAP, AL, 100 µF, 35 V, +/- 20%, SMD"
D1: "Diode, Schottky, 60 V, 2 A, SMB"
D2 D10: "Diode, TVS, Uni, 27 V, 40 W, SOT-23"
D3 D4: "Diode, Schottky, 30 V, 1 A, SOD-323F"
D5: "Diode, Schottky, 60 V, 1 A, SOD-123F"
D6: "LED, Orange, SMD"
D7 D8 D9: "LED, Red, SMD"
D11 D12: "Diode, Switching, 350 V, 0.225 A, SOD-123"
FID1 FID2 FID3 FID4 FID5 FID6: "Fiducial mark.  There is nothing to buy or mount."
J1/J3: library part BoosterPack_40pin_J1J3, "Receptacle, 2.54mm, 10x2, Tin, TH"
J2/J4: library part BoosterPack_40pin_J2J4, "Receptacle, 2.54mm, 10x2, Tin, TH"
J5: "Power Jack, 2.5mm, R/A, SMT"
J6: "Header, 2.54 mm, 3x1, Tin, TH"
J7: "Header, 2.54mm, 2x2, Gold, SMT"
J8: "Receptacle, 2.54mm, 6x1, Gold, R/A, Black, TH"
J9 J11 J12 J14: "Header, 100mil, 2x1, Tin, TH"
J10 J13: "Header, 2.54mm, 6x1, Gold, TH"
L1: "Inductor, Shielded Drum Core, Ferrite, 10 µH, 1.15 A, 0.16 ohm, SMD"
L2: "Inductor, Drum Core, Ferrite, 10 µH, 1.15 A, 0.18 ohm, SMD"
Logo1 Logo4 Logo5: library part TI_Logo, "Texas Instrument Corporate Signature"
Logo2: library part Pb-Free
Logo3: library part FCC_disclaimer, "FCC_disclaimer"
Q1: "MOSFET, N-CH, 60 V, 0.115 A, SOT-363"
Q2: "MOSFET, P-CH, -30 V, -1.8 A, superSOT-6"
Q3: "MOSFET, N-CH, 100 V, 0.17 A, SOT-23"
R1: "RES, 10, 5%, 0.75 W, 2010"
R2: "RES, 100 k, 1%, 0.063 W, 0402"
R3: "RES, 2.2 M, 1%, 0.25 W, 1206"
R4: "RES, 383 k, 1%, 0.063 W, 0402"
R5: "RES, 33, 5%, 0.75 W, AEC-Q200 Grade 0, 2010"
R6: "RES, 51.1 k, 1%, 0.063 W, 0402"
R7 R9 R18: "RES, 10.0 k, 1%, 0.063 W, 0402"
R8: "RES, 51 k, 5%, 0.1 W, 0603"
R10: "RES, 10 k, 5%, 0.1 W, 0603"
R11 R12 R14 R16: "RES, 0, 5%, 0.063 W, 0402"
R13: "RES, 100 k, 5%, 0.063 W, 0402"
R15 R17 R32 R34 R35 R36 R39 R40: "RES, 0, 5%, 0.25 W, 1206"
R19 R21 R25 R28 R29 R30 R31: "RES, 1.0 k, 5%, 0.1 W, 0603"
R20: "RES, 1.0 k, 5%, 0.75 W, AEC-Q200 Grade 0, 2010"
R22 R23 R24 R26 R27: "RES, 100 k, 5%, 0.1 W, 0603"
R33: "RES, 2.0 k, 5%, 0.063 W, 0402"
R37: "RES, 100, 5%, 0.125 W, 0805"
R38: "RES, 2.7 k, 5%, 0.25 W, 1206"
R41: "RES, 100, 1%, 0.1 W, 0603"
SH-J1: "Shunt, 2.54mm, Gold, Black"
T1: "Transformer, 3 mH, SMT"
TP1 TP2 TP3 TP4 TP5: library part 5015, "Test Point, Miniature, SMT"
U1: "28V, 0.5A Step-Down Converter with Sleep Mode, DQC0010A"
U2: "SIMPLE SWITCHER 24Vout, 2.1A Step-Up Voltage Regulator in SOT-23, DBV0005A"
U3: "PGA460TPWRQ1, PW0016A"
U4: "16-BIT TO 8-BIT MULTIPLEXER/DEMULTIPLEXER GIGABIT ETHERNET LAN SWITCH WITH POWER DOWN MODE, RUA0042A"
U5: "Dual Comparator, PW0008A"
U6: "512Kbit SPI Serial SRAM with SDI and SQI Interface,"
U7: "Ultrasonic Transducer, 6 VPP, 40 kHz, 4500 pF, -20 to 60 degC, SMD, 4-Pin Body 5.2 x 5.2 mm"
ZZ1 ZZ2 ZZ3 ZZ4 ZZ5: library part AssemblyNote

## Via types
v1: diameter 32, hole 12, Top Layer to Bottom Layer, tented both sides, 125 vias
v2: diameter 50, hole 28, Top Layer to Bottom Layer, 28 vias
v3: diameter 19.68, hole 7.87, Top Layer to Bottom Layer, tented both sides, 14 vias
v4: diameter 80, hole 55, Top Layer to Bottom Layer, 12 vias

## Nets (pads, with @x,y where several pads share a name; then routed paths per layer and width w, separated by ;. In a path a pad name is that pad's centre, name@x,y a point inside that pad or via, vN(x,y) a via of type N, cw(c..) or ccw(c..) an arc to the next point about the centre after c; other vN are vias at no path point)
3V3LP: J1/J3.1 R13.2 R19.1 R21.2 R25.2 R26.1 U4.39 U6.8 | length 3732.6
  Top Layer w10: 1178,1050 1178.53,1049.47 U4.39@1178.53,992.18 ; U6.8@1408.39,600.8 1408.39,645.39 1449.5,686.5 R25.2@1449.5,922 ; v1(1566,1160) 1599.5,1160
  Top Layer w20: J1/J3.1@260,1100 J1/J3.1@250,1100 ; R13.2@749.38,202 647,202 590,145 209,145 144,210 144,994 J1/J3.1@250,1100 ; R25.2@1449,922.5 1416.5,922.5 R26.1@1385,954 1372,954 1276,1050 1178,1050 300,1050 J1/J3.1@250,1100 ; R19.1@1601,1127.5 R21.2@1601,1195.5
  Bottom Layer w10: v1(1284,1069) 1548,1069 1566,1087 v1(1566,1160)
5VLP: D3.1 J1/J3.21 J7.3 | length 1964
  Top Layer w10: J7.3@1072,1576 J7.3@1072,1617.6
  Top Layer w30: v2@1667,1480 1710.51,1480
  Top Layer w50: J1/J3.21@350,1100 383,1133 v2(757,1133) ; J7.3@1072,1576 v2(1136,1512)
  Bottom Layer w40: 989,1342 1008.87,1322.13 1644.13,1322.13 1667,1345 v2(1667,1481)
  Bottom Layer w50: v2(757,1133) v2(1136,1512)
AVDD: C7.1 U3.16 | length 59.8
  Top Layer w10: C7.1@944.5,494 U3.16@1004.29,494
COM_PD: J2/J4.18 U4.5 | length 2335.9
  Top Layer w10: v1(926,883) 933,883 940.13,890.13 1047.59,890.13 1052.2,894.74 U4.5@1081.09,894.74
  Bottom Layer w10: v1(926,883) 908.13,865.13 908.13,822.04 1396.04,334.13 1400.87,334.13 1486,249 2083,249 2120,286 2120,830 J2/J4.18@2050,900
COM_SEL: J2/J4.17 U4.13 | length 2108.4
  Top Layer w10: v1@1021.49,647.51 1025,651.01 v1(1025,656) 1025,686.72 1051.48,713.2 1051.48,725.35 1062.48,736.35 1080.18,736.35 U4.13@1081.09,737.26 ; J2/J4.17@2050,800 2151,699 v1(2151,692)
  Bottom Layer w10: v1@1021.49,647.51 1046.13,647.51 1541.63,152 2086,152 2140,206 v1@2140,693.64
DECPL: J8.6 R11.1 R12.1 U3.13 | length 708.3
  Top Layer w10: R11.1@796.62,335 R12.1@796.62,382 ; R12.1@805,384 814,393 1040.72,393 1081.2,433.48 U3.13@1081.2,494.14 ; v1(843,292) 843,391 845,393
  Bottom Layer w10: v1(843,292) 843,145 J8.6@882,106
DECPL_A: J1/J3.2 R12.2 | length 973.9
  Top Layer w10: R12.2@749.38,382 749.38,400.38 v1(773,424)
  Bottom Layer w10: J1/J3.2@250,1000 300,950 381,950 418,913 418,639 633,424 v1(773,424)
DECPL_D: J1/J3.5 R11.2 | length 916.3
  Top Layer w10: v1(555,286) 604,335 R11.2@749.38,335
  Bottom Layer w10: J1/J3.5@250,700 236,700 189,653 189,477 216,450 391,450 v1(555,286)
DECPL_DD: J10.1
DECPL_XD: J13.1 Q3.1 | length 463.9
  Bottom Layer w10: J13.1@107.05,2107 366,2107 470.76,2211.76 Q3.1@470.76,2268.6
DS1_LED: D9.1 J2/J4.38 | length 608.7
  Top Layer w10: J2/J4.38@1950,900 1883,967 1883,1180.47 D9.1@2095.5,1392.97
F_DIAG_LED: D8.1 J2/J4.39 | length 422.9
  Top Layer w10: J2/J4.39@1950,1000 1903.29,1046.71 1903.29,1131.82 D8.1@2095.47,1324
